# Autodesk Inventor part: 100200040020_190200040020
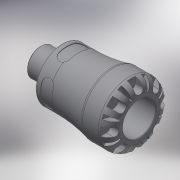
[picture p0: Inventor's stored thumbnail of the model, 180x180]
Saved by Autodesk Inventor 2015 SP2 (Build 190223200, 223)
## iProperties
Created: 2016-12
Part Number: 100200040020_190200040020
Material: Generic
Description: PLASSON MALE ADAPTOR 40X2" SERIES 1
Document SubType Name: Modeling
Designer: KIM
Mass: 447.839 g
Surface Area: 722.341 cm^2
Volume: 447.839 cm^3
Density: 1 g/cm^3
Appearance: Default
Author: KIM
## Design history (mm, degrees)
derived "1002.ipt"
feature "Solid1::1002.ipt"
tag "TaggingFeature1"
body "Solid1"
other parameters: "d1" = 30.66, "d6" = 73, "d8" = 63, "d13" = 8, "d14" = 8, "d15" = 0, "d17" = 360 deg, "d19" = 8 deg, "d20" = 0.8, "d21" = 0.8, "d22" = 8 deg, "d24" = 0, "d26" = 360 deg, "d32" = 0.925, "d33" = 7, "d34" = 59.614, "d35" = 5, "d38" = 25, "d39" = 1.78842, "d42" = 14, "d43" = 9.2, "d45" = 15.68, "d46" = 0, "d59" = 360 deg, "d61" = 11.9, "d62" = 0.8, "d64" = 0, "d65" = 0.7, "l_" = 73, "R_" = 59.614, "l_2" = 25, "d9" = 10
